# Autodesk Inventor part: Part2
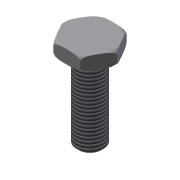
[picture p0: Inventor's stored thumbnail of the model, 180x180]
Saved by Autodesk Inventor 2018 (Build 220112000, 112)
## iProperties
Shininess: 77.0
Angle Display Precision: 2
Document Length Units: 11269
Document Angle Units: 11279
Document Time Units: 11290
Document Mass Units: 11283
Document Length Units Precision: 3
Document Angle Units Precision: 2
Created: 2002-01
Part Number: Part2
Document SubType Name: Modeling
Designer: ***
Density: 1 g/cm^3
Material: Generic
Appearance: Default
Density: 0.0
Volumn: 0.0
Area: 0.0
PropertySet Name: Model Information
Control State: 0
Master: False
Checked Out: False
Author: ***
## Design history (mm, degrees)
sketch "Sketch1"
  geometry: C1 r 20 at (0, 0)
  constraints: 1 centre point
  dimensions: "d0" = 40 diameter of C1
extrude "Extrusion1" new body sketch "Sketch1" distance "d1" = 10; taper "d2" = 0 deg
fillet "Fillet1" dims "d3" = 3
sketch "Sketch3"
  geometry: L1 (20, 0)-(10, -17.321); L2 (10, -17.321)-(-10, -17.321); L3 (-10, -17.321)-(-20, 0); L4 (-20, 0)-(-10, 17.321); L5 (-10, 17.321)-(10, 17.321); L6 (10, 17.321)-(20, 0); C1 r 17 at (0, 0) reference; 1 further point
  constraints: 12 end point, 1 coincident, 11 other
extrude "Extrusion3" sketch "Sketch3" distance "d7" = 10; taper "d8" = 0 deg
sketch "Sketch2"
  geometry: C1 r 10 at (0, 0); 1 further point
  constraints: 1 centre point, 1 coincident
  dimensions: "d4" = 20 diameter of C1
extrude "Extrusion2" join sketch "Sketch2" distance "d5" = 60; taper "d6" = 0 deg
chamfer "Chamfer1" distance "d9" = 2; stored, may be unused: second distance "d10" = 2, angle "d13" = 45 deg
thread "Thread1" dims "d11" = 10, "d12" = 0
body "Solid1"
